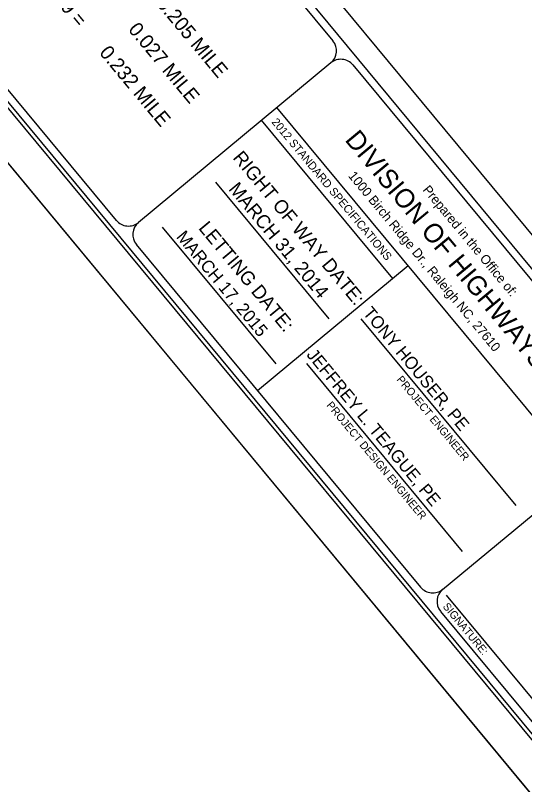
# Model space of a CAD drawing. Extents: x 2054826 to 2060231, y 685508 to 690809.
# Drawn here: x 2058198 to 2058687, y 687645 to 688383 of the extents above; entities that cross this region are included whole.
import ezdxf

# ---------------------------------------------------------------- set-up
doc = ezdxf.new("R2010")
doc.units = 0
for name, color, linetype in [('Old_Level_11', 7, 'Continuous'), ('Old_Level_21', 7, 'Continuous'), ('Sheet Cutting Line CELL', 7, 'Continuous'), ('Sheet Data Field CELL', 7, 'Continuous'), ('Sheet Plot Border Inside CELL', 7, 'Continuous'), ('Sheet Plot Border Outside CELL', 7, 'Continuous'), ('Sheet Title CELL', 7, 'Continuous')]:
    doc.layers.add(name, color=color, linetype=linetype)

msp = doc.modelspace()

# ---------------------------------------------------------------- linework, layer by layer
at = {"layer": 'Old_Level_21'}
msp.add_lwpolyline([(2058588.27, 689338), (2059498.4, 688240.46), (2058988.43, 687817.56), (2058078.29, 688915.11)], close=True, dxfattribs=at)
at = {"layer": 'Sheet Cutting Line CELL'}
msp.add_line((2057348.74, 689256.87), (2058961.15, 687312.44), dxfattribs=at)
at = {"layer": 'Sheet Plot Border Inside CELL'}
msp.add_lwpolyline([(2057387.09, 689263.34), (2058982.75, 687339.12), (2060201.02, 688349.37), (2058605.36, 690273.59)], close=True, dxfattribs=at)
at = {"layer": 'Sheet Plot Border Outside CELL'}
msp.add_lwpolyline([(2060231.25, 688365.67), (2058618.84, 690310.09), (2057348.74, 689256.87), (2058961.15, 687312.44)], close=True, dxfattribs=at)
at = {"layer": 'Sheet Title CELL'}
for p, q in [((2057819.13, 689194.85), (2059178.76, 687555.25)), ((2058138.88, 688797.47), (2058502.73, 688358.7)), ((2058500.77, 688337.59), (2058316.03, 688184.4)), ((2058521.9, 688335.62), (2058794.78, 688006.55)), ((2058741.12, 687942.57), (2058449.1, 688294.75)), ((2058560.33, 688130.63), (2058434.38, 688282.54)), ((2058499.34, 688091.76), (2058390.43, 688223.1)), ((2058448.23, 688048.59), (2058339.32, 688179.93)), ((2058524.05, 688174.41), (2058524.05, 688174.41)), ((2058444.85, 688157.44), (2058444.85, 688157.44)), ((2058575.06, 688142.85), (2058430.44, 688022.93)), ((2058529.71, 688091.8), (2058678.25, 687912.64)), ((2058477.41, 688049.12), (2058627.02, 687868.7)), ((2058608.05, 687832.22), (2058792.79, 687985.41)), ((2058611.54, 687826.74), (2058750.85, 687658.72))]:
    msp.add_line(p, q, dxfattribs=at)
for points in [[(2057547.07, 689076.42), (2058964.15, 687367.54)], [(2057931.05, 688625.12), (2058294.89, 688186.36)], [(2058314.06, 688163.27), (2058586.93, 687834.19)], [(2058606.09, 687811.11), (2058797.38, 687580.44)]]:
    msp.add_lwpolyline(points, dxfattribs=at)
for centre, start, end in [((2058491.25, 688349.18), 309.66721, 39.66721), ((2058510.4, 688326.09), 39.66721, 129.66721), ((2058306.51, 688195.98), 219.66721, 309.66721), ((2058325.66, 688172.89), 129.66721, 219.66721), ((2058598.55, 687843.81), 219.66721, 309.66721), ((2058617.7, 687820.72), 129.66721, 219.66721)]:
    msp.add_arc(centre, 15, start, end, dxfattribs=at)

# ---------------------------------------------------------------- texts
at = {"layer": 'Old_Level_11'}
for s, p in [('TOTAL LENGTH TIP PROJECT B-4659 = ', (2058038.76, 688633.85)), ('0.205 MILE', (2058332.83, 688394.06)), ('0.027 MILE', (2058305.7, 688369.38)), ('0.232 MILE', (2058277.93, 688347.15))]:
    msp.add_text(s, height=13.672, rotation=309.74237, dxfattribs=at).set_placement(p)
at = {"layer": 'Sheet Data Field CELL'}
for s, height, p in [('MARCH 31, 2014', 13.1251, (2058401.99, 688216.22)), ('MARCH 17, 2015    ', 12, (2058351.82, 688170.35)), ('       TONY HOUSER, PE      ', 12, (2058511.05, 688121.24)), ('      JEFFREY L. TEAGUE, PE ', 12, (2058459.79, 688077.68))]:
    msp.add_text(s, height=height, rotation=309.66721, dxfattribs=at).set_placement(p)
at = {"layer": 'Sheet Title CELL'}
for s, height, p in [('2012 STANDARD SPECIFICATIONS', 7.8, (2058443.46, 688280.63)), ('DIVISION OF HIGHWAYS', 18.2808, (2058513.6, 688263.49)), ('RIGHT OF WAY DATE: ', 13.1247, (2058406.07, 688246.3)), ('1000 Birch Ridge Dr., Raleigh NC, 27610', 9, (2058517.01, 688228.95)), ('Prepared in the Office of:', 8.9991, (2058588.48, 688215.46)), ('LETTING DATE:', 13.1247, (2058373.13, 688178.75)), ('PROJECT ENGINEER', 7.4992, (2058563.51, 688033.41)), ('PROJECT DESIGN ENGINEER', 7.4992, (2058496.16, 688008.74)), ('SIGNATURE:', 7.499, (2058607.76, 687815.56))]:
    msp.add_text(s, height=height, rotation=309.66721, dxfattribs=at).set_placement(p)

doc.saveas('drawing.dxf')
